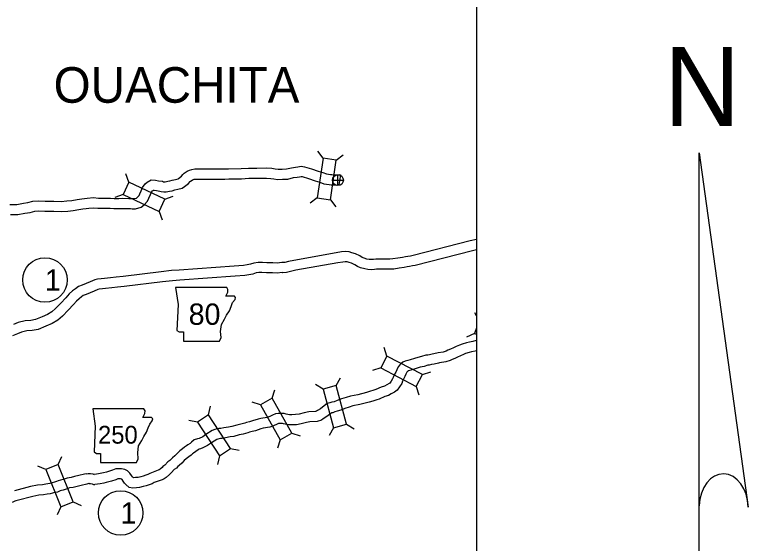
# Model space of a CAD drawing. Extents: x 1382482 to 1385815, y 1168351 to 1170484.
# Drawn here: x 1383234.6 to 1383452.3, y 1169980.1 to 1170137 of the extents above; entities that cross this region are included whole.
import ezdxf

# ---------------------------------------------------------------- set-up
doc = ezdxf.new("R2010")
doc.units = 0
for name, color, linetype in [('10', 7, 'Continuous'), ('20', 7, 'Continuous'), ('21', 7, 'Continuous'), ('26', 7, 'Continuous'), ('8', 7, 'Continuous'), ('Default', 7, 'Continuous'), ('R_Draft', 7, 'Continuous'), ('R_No Plot', 7, 'Continuous')]:
    doc.layers.add(name, color=color, linetype=linetype)

msp = doc.modelspace()

# ---------------------------------------------------------------- linework, layer by layer
at = {"layer": '10'}
msp.add_line((1383331.28, 1170089.42), (1383330.79, 1170086.46), dxfattribs=at)
for points in [[(1383233.12, 1170080.63), (1383235.23, 1170080.67), (1383237.16, 1170080.99), (1383238.51, 1170081.19), (1383239.97, 1170081.62), (1383241.64, 1170081.75), (1383243.59, 1170081.61), (1383246.24, 1170081.64), (1383248.38, 1170081.51), (1383250.08, 1170081.67), (1383251.52, 1170081.82), (1383253.16, 1170082.09), (1383254.48, 1170082.31), (1383255.33, 1170082.37), (1383256.11, 1170082.53), (1383257.99, 1170082.69), (1383259.45, 1170082.54), (1383261.24, 1170082.52), (1383262.99, 1170082.49), (1383264.08, 1170082.43), (1383265.44, 1170082.44), (1383266.66, 1170082.46), (1383268.48, 1170082.42), (1383269.06, 1170082.42), (1383269.61, 1170082.38), (1383270.13, 1170082.36), (1383270.76, 1170082.53), (1383270.92, 1170082.66), (1383271.49, 1170083.31), (1383271.7, 1170083.77), (1383272.12, 1170084.68), (1383272.48, 1170085.7), (1383273.27, 1170086.74), (1383273.93, 1170087.28), (1383275.05, 1170087.95), (1383276.39, 1170087.88), (1383277.24, 1170087.69), (1383278.41, 1170087.51), (1383278.74, 1170087.39), (1383278.94, 1170087.37), (1383279.26, 1170087.38), (1383280.01, 1170087.51), (1383280.64, 1170087.62), (1383281.32, 1170087.84), (1383282.29, 1170088.08), (1383283.11, 1170088.27), (1383283.23, 1170088.34), (1383284.07, 1170089.05), (1383284.47, 1170089.49), (1383284.88, 1170089.93), (1383285.79, 1170090.48), (1383286.45, 1170090.79), (1383287.12, 1170091.02), (1383288.09, 1170091.18), (1383290.2, 1170091.18), (1383296.87, 1170091.16), (1383298.06, 1170091.25), (1383301.82, 1170091.28), (1383304, 1170091.42), (1383305.23, 1170091.42), (1383306.43, 1170091.44), (1383309.39, 1170091.47), (1383310.93, 1170091.36), (1383311.88, 1170091.21), (1383312.77, 1170091.09), (1383313.98, 1170091.14), (1383315.24, 1170091.17), (1383316.69, 1170091.53), (1383317.93, 1170091.74), (1383318.65, 1170091.85), (1383319.63, 1170091.98), (1383320.57, 1170091.81), (1383322.72, 1170091.16), (1383324.7, 1170090.48), (1383326.08, 1170090.08), (1383327.1, 1170089.7), (1383328.27, 1170089.54), (1383328.74, 1170089.49), (1383329.5, 1170089.46), (1383330.15, 1170089.42), (1383330.93, 1170089.49), (1383331.28, 1170089.42)], [(1383233.32, 1170077.63), (1383235.51, 1170077.68), (1383237.63, 1170078.02), (1383239.16, 1170078.25), (1383240.51, 1170078.65), (1383241.65, 1170078.74), (1383243.5, 1170078.61), (1383246.16, 1170078.64), (1383248.44, 1170078.5), (1383250.39, 1170078.69), (1383251.92, 1170078.85), (1383253.65, 1170079.13), (1383254.82, 1170079.33), (1383255.75, 1170079.39), (1383256.55, 1170079.56), (1383257.97, 1170079.68), (1383259.28, 1170079.55), (1383261.2, 1170079.52), (1383262.88, 1170079.49), (1383264.01, 1170079.42), (1383265.49, 1170079.44), (1383266.66, 1170079.46), (1383268.44, 1170079.42), (1383268.95, 1170079.42), (1383269.47, 1170079.38), (1383270.47, 1170079.35), (1383272.16, 1170079.79), (1383273.02, 1170080.5), (1383274.02, 1170081.66), (1383274.42, 1170082.5), (1383274.91, 1170083.55), (1383275.16, 1170084.26), (1383275.44, 1170084.65), (1383275.65, 1170084.82), (1383275.8, 1170084.91), (1383275.98, 1170084.9), (1383276.69, 1170084.74), (1383277.65, 1170084.6), (1383278.03, 1170084.45), (1383278.82, 1170084.36), (1383279.57, 1170084.38), (1383280.52, 1170084.55), (1383281.36, 1170084.7), (1383282.15, 1170084.95), (1383282.99, 1170085.17), (1383284.29, 1170085.46), (1383285, 1170085.92), (1383286.14, 1170086.87), (1383286.67, 1170087.44), (1383286.79, 1170087.57), (1383287.23, 1170087.84), (1383287.58, 1170088.01), (1383287.85, 1170088.1), (1383288.35, 1170088.18), (1383290.2, 1170088.18), (1383296.97, 1170088.16), (1383298.17, 1170088.25), (1383301.93, 1170088.28), (1383304.1, 1170088.42), (1383305.26, 1170088.42), (1383306.47, 1170088.44), (1383309.3, 1170088.47), (1383310.59, 1170088.38), (1383311.45, 1170088.24), (1383312.63, 1170088.08), (1383314.08, 1170088.14), (1383315.64, 1170088.18), (1383317.29, 1170088.59), (1383318.4, 1170088.77), (1383319.08, 1170088.88), (1383319.56, 1170088.94), (1383319.87, 1170088.89), (1383321.79, 1170088.31), (1383323.79, 1170087.62), (1383325.15, 1170087.22), (1383326.37, 1170086.78), (1383327.9, 1170086.56), (1383328.53, 1170086.49), (1383329.35, 1170086.46), (1383330.19, 1170086.41), (1383330.79, 1170086.46)], [(1383371.62, 1170070.23), (1383369.73, 1170069.81), (1383352.84, 1170065.49), (1383352.07, 1170065.34), (1383351.24, 1170065.19), (1383350.59, 1170065.1), (1383349.65, 1170064.92), (1383348.25, 1170064.67), (1383346.81, 1170064.46), (1383345.88, 1170064.42), (1383344.7, 1170064.42), (1383343.82, 1170064.41), (1383342.69, 1170064.44), (1383341.79, 1170064.42), (1383341.07, 1170064.35), (1383340.32, 1170064.29), (1383339.76, 1170064.33), (1383339.11, 1170064.44), (1383338.26, 1170064.66), (1383337.72, 1170064.92), (1383336.98, 1170065.36), (1383335.69, 1170065.97), (1383334.68, 1170066.32), (1383333.81, 1170066.53), (1383332.68, 1170066.66), (1383331.6, 1170066.53), (1383330.04, 1170066.33), (1383317.47, 1170064.05), (1383315.83, 1170063.69), (1383314.76, 1170063.45), (1383314.06, 1170063.4), (1383313.83, 1170063.4), (1383312.44, 1170063.23), (1383311.19, 1170063.31), (1383309.46, 1170063.32), (1383308.12, 1170063.41), (1383306.87, 1170063.45), (1383305.58, 1170063.22), (1383304.55, 1170062.9), (1383303.55, 1170062.69), (1383302.52, 1170062.55), (1383299.76, 1170062.34), (1383283.39, 1170061.17), (1383281.08, 1170061), (1383278.07, 1170060.64), (1383266.76, 1170059.26), (1383264.72, 1170059.03), (1383263.06, 1170058.84), (1383261.25, 1170058.66), (1383260.28, 1170058.58), (1383259.13, 1170058.43), (1383258.32, 1170058.24), (1383256.99, 1170057.71), (1383254.6, 1170056.72), (1383253.48, 1170056.26), (1383252.59, 1170055.63), (1383251.78, 1170055), (1383250.75, 1170054.1), (1383249.75, 1170052.95), (1383248.3, 1170051.31), (1383246.68, 1170049.72), (1383245.58, 1170048.74), (1383244.34, 1170047.96), (1383242.69, 1170047.31), (1383240.72, 1170046.46), (1383239.34, 1170046.24), (1383237.71, 1170046.09), (1383235.65, 1170045.61), (1383234.26, 1170044.99)], [(1383371.62, 1170067.16), (1383370.43, 1170066.89), (1383353.49, 1170062.56), (1383352.61, 1170062.39), (1383351.72, 1170062.23), (1383351.08, 1170062.14), (1383350.19, 1170061.97), (1383348.73, 1170061.71), (1383347.09, 1170061.47), (1383345.94, 1170061.42), (1383344.72, 1170061.42), (1383343.8, 1170061.41), (1383342.68, 1170061.44), (1383341.98, 1170061.42), (1383341.34, 1170061.36), (1383340.34, 1170061.28), (1383339.4, 1170061.35), (1383338.49, 1170061.5), (1383337.24, 1170061.82), (1383336.29, 1170062.27), (1383335.56, 1170062.71), (1383334.56, 1170063.18), (1383333.83, 1170063.43), (1383333.28, 1170063.57), (1383332.69, 1170063.64), (1383331.97, 1170063.55), (1383330.5, 1170063.36), (1383318.06, 1170061.11), (1383316.48, 1170060.76), (1383315.21, 1170060.48), (1383314.12, 1170060.39), (1383313.95, 1170060.4), (1383312.53, 1170060.22), (1383311.08, 1170060.31), (1383309.36, 1170060.33), (1383307.97, 1170060.41), (1383307.09, 1170060.44), (1383306.29, 1170060.3), (1383305.29, 1170059.99), (1383304.07, 1170059.74), (1383302.84, 1170059.56), (1383299.97, 1170059.35), (1383283.6, 1170058.18), (1383281.37, 1170058.02), (1383278.43, 1170057.66), (1383267.11, 1170056.28), (1383265.05, 1170056.05), (1383263.38, 1170055.86), (1383261.52, 1170055.67), (1383260.59, 1170055.6), (1383259.67, 1170055.47), (1383259.21, 1170055.37), (1383258.12, 1170054.93), (1383255.75, 1170053.95), (1383254.94, 1170053.61), (1383254.38, 1170053.22), (1383253.69, 1170052.68), (1383252.88, 1170051.98), (1383252.01, 1170050.97), (1383250.48, 1170049.25), (1383248.73, 1170047.53), (1383247.39, 1170046.33), (1383245.7, 1170045.28), (1383243.83, 1170044.54), (1383241.56, 1170043.56), (1383239.72, 1170043.26), (1383238.19, 1170043.12), (1383236.61, 1170042.76), (1383235.42, 1170042.22), (1383233.91, 1170041.64)], [(1383371.62, 1170040.29), (1383371.5, 1170040.26), (1383370.59, 1170039.99), (1383369.54, 1170039.8), (1383368.67, 1170039.61), (1383367.4, 1170039.21), (1383366.62, 1170038.92), (1383365.65, 1170038.46), (1383364.79, 1170038.09), (1383363.93, 1170037.68), (1383363.17, 1170037.35), (1383362.68, 1170037.12), (1383361.79, 1170036.81), (1383360.31, 1170036.58), (1383359.87, 1170036.54), (1383358.46, 1170036.2), (1383357.71, 1170036.05), (1383357.21, 1170035.94), (1383356.62, 1170035.9), (1383355.35, 1170035.47), (1383354.26, 1170035.24), (1383353.21, 1170034.95), (1383351.96, 1170034.55), (1383351.29, 1170034.35), (1383350.51, 1170034.1), (1383349.83, 1170033.86), (1383349.19, 1170033.32), (1383348.93, 1170033.09), (1383348.42, 1170032.48), (1383347.97, 1170031.61), (1383347.66, 1170030.91), (1383347.22, 1170030.08), (1383346.9, 1170029.28), (1383346.74, 1170028.85), (1383346.33, 1170028.17), (1383345.92, 1170027.62), (1383345.73, 1170027.46), (1383345.01, 1170027.12), (1383344.3, 1170026.74), (1383343.39, 1170026.41), (1383341.73, 1170025.7), (1383341.19, 1170025.54), (1383339.92, 1170025.13), (1383339.01, 1170024.85), (1383336.38, 1170024.16), (1383334.23, 1170023.76), (1383332.95, 1170023.38), (1383331.53, 1170022.91), (1383330.32, 1170022.45), (1383329.4, 1170022.11), (1383328.73, 1170021.93), (1383328.13, 1170021.73), (1383327.32, 1170021.54), (1383326.46, 1170020.88), (1383325.3, 1170020.01), (1383324.42, 1170019.49), (1383324.19, 1170019.3), (1383323.85, 1170019.2), (1383321.84, 1170019.08), (1383320.49, 1170018.84), (1383318.98, 1170018.45), (1383317.92, 1170018.26), (1383316.76, 1170018.2)], [(1383371.62, 1170037.17), (1383371.29, 1170037.07), (1383370.13, 1170036.86), (1383369.45, 1170036.71), (1383368.37, 1170036.36), (1383367.78, 1170036.15), (1383366.9, 1170035.73), (1383366.03, 1170035.35), (1383365.17, 1170034.95), (1383364.41, 1170034.62), (1383363.79, 1170034.33), (1383362.52, 1170033.89), (1383360.68, 1170033.6), (1383360.35, 1170033.57), (1383359.11, 1170033.27), (1383358.32, 1170033.11), (1383357.63, 1170032.96), (1383357.22, 1170032.94), (1383356.14, 1170032.57), (1383354.96, 1170032.32), (1383354.07, 1170032.08), (1383352.86, 1170031.69), (1383352.18, 1170031.48), (1383351.45, 1170031.25), (1383351.35, 1170031.22), (1383351.14, 1170031.03), (1383351.07, 1170030.98), (1383350.94, 1170030.82), (1383350.67, 1170030.3), (1383350.36, 1170029.61), (1383349.95, 1170028.82), (1383349.69, 1170028.19), (1383349.45, 1170027.53), (1383348.82, 1170026.5), (1383348.12, 1170025.55), (1383347.35, 1170024.91), (1383346.36, 1170024.44), (1383345.54, 1170023.99), (1383344.48, 1170023.62), (1383342.74, 1170022.87), (1383342.07, 1170022.67), (1383340.83, 1170022.28), (1383339.83, 1170021.96), (1383337.03, 1170021.23), (1383334.93, 1170020.84), (1383333.86, 1170020.52), (1383332.54, 1170020.08), (1383331.36, 1170019.64), (1383330.31, 1170019.25), (1383329.59, 1170019.06), (1383328.96, 1170018.85), (1383328.63, 1170018.77), (1383328.27, 1170018.49), (1383326.97, 1170017.52), (1383326.14, 1170017.02), (1383325.63, 1170016.61), (1383324.4, 1170016.22), (1383322.19, 1170016.1), (1383321.14, 1170015.91), (1383319.62, 1170015.51), (1383318.26, 1170015.27), (1383316.92, 1170015.21)], [(1383316.88, 1170018.2), (1383316.16, 1170018.22), (1383315.15, 1170018.41), (1383314.52, 1170018.64), (1383312.73, 1170018.61), (1383311.95, 1170018.55), (1383311.08, 1170018.06), (1383310.33, 1170017.7), (1383309.56, 1170017.46), (1383307.68, 1170017.15), (1383306.8, 1170016.89), (1383305.18, 1170016.38), (1383304.25, 1170016.13), (1383303.39, 1170015.9), (1383302.85, 1170015.72), (1383301.7, 1170015.41), (1383300.49, 1170015.15), (1383299.02, 1170014.76), (1383298.01, 1170014.59), (1383296.63, 1170014.35), (1383295.73, 1170014.2), (1383295.13, 1170014.14), (1383294.02, 1170013.87), (1383293.19, 1170013.55), (1383291.35, 1170012.35), (1383290.37, 1170011.68), (1383289.3, 1170011.18), (1383288.88, 1170011.04), (1383287.89, 1170010.8), (1383287.08, 1170010.09), (1383286.66, 1170009.74), (1383285.97, 1170009.33), (1383285.54, 1170009.03), (1383285, 1170008.58), (1383284.4, 1170008.09), (1383283.59, 1170007.5), (1383282.76, 1170006.73), (1383282.1, 1170006), (1383281.45, 1170005.47), (1383280.9, 1170005), (1383280.61, 1170004.66), (1383279.99, 1170004.27), (1383279.1, 1170003.28), (1383278.59, 1170002.87), (1383278.36, 1170002.58), (1383277.79, 1170002.08), (1383277.46, 1170001.88), (1383277.17, 1170001.74), (1383276.13, 1170001.39), (1383274.69, 1170000.81), (1383274.12, 1170000.51), (1383273.49, 1170000.28), (1383272.71, 1170000), (1383272.01, 1169999.82), (1383271.18, 1169999.64), (1383270.4, 1169999.57), (1383269.84, 1169999.51), (1383269.73, 1169999.61), (1383269.59, 1169999.78), (1383269.26, 1170000.24), (1383268.8, 1170000.94), (1383268.08, 1170001.61), (1383267.23, 1170001.99), (1383266.31, 1170002.22), (1383265.46, 1170002.19), (1383264.58, 1170002.14), (1383263.58, 1170001.77), (1383262.41, 1170001.35), (1383261.81, 1170001.2), (1383260.95, 1170000.98), (1383260.44, 1170000.85), (1383259.46, 1170000.69), (1383258.82, 1170000.59), (1383258.21, 1170000.55)], [(1383316.8, 1170015.2), (1383315.84, 1170015.23), (1383314.35, 1170015.51), (1383314.02, 1170015.63), (1383312.88, 1170015.61), (1383312.84, 1170015.61), (1383312.46, 1170015.4), (1383311.44, 1170014.9), (1383310.26, 1170014.54), (1383308.35, 1170014.22), (1383307.68, 1170014.02), (1383306.02, 1170013.5), (1383305.02, 1170013.22), (1383304.26, 1170013.03), (1383303.73, 1170012.85), (1383302.39, 1170012.49), (1383301.19, 1170012.24), (1383299.66, 1170011.82), (1383298.51, 1170011.63), (1383297.13, 1170011.39), (1383296.13, 1170011.23), (1383295.63, 1170011.17), (1383294.91, 1170011), (1383294.56, 1170010.87), (1383293.02, 1170009.86), (1383291.85, 1170009.06), (1383290.4, 1170008.39), (1383289.71, 1170008.16), (1383289.32, 1170008.06), (1383289.03, 1170007.81), (1383288.39, 1170007.28), (1383287.6, 1170006.81), (1383287.38, 1170006.65), (1383286.92, 1170006.27), (1383286.24, 1170005.71), (1383285.5, 1170005.18), (1383284.89, 1170004.61), (1383284.17, 1170003.82), (1383283.37, 1170003.16), (1383283.03, 1170002.88), (1383282.61, 1170002.37), (1383281.94, 1170001.95), (1383281.16, 1170001.08), (1383280.72, 1170000.74), (1383280.54, 1170000.5), (1383279.57, 1169999.66), (1383278.91, 1169999.25), (1383278.32, 1169998.96), (1383277.17, 1169998.57), (1383275.95, 1169998.08), (1383275.34, 1169997.76), (1383274.52, 1169997.46), (1383273.59, 1169997.12), (1383272.7, 1169996.9), (1383271.64, 1169996.67), (1383270.69, 1169996.58), (1383269.61, 1169996.47), (1383268.56, 1169996.67), (1383267.57, 1169997.5), (1383267.2, 1169997.96), (1383266.78, 1169998.54), (1383266.49, 1169998.99), (1383266.4, 1169999.08), (1383266.25, 1169999.14), (1383265.99, 1169999.21), (1383265.58, 1169999.2), (1383265.21, 1169999.17), (1383264.61, 1169998.95), (1383263.28, 1169998.48), (1383262.54, 1169998.3), (1383261.69, 1169998.08), (1383261.06, 1169997.91), (1383259.95, 1169997.73), (1383259.15, 1169997.6), (1383258.38, 1169997.56)], [(1383255.81, 1170000.72), (1383255.76, 1170000.71), (1383255.26, 1170000.59), (1383253.61, 1170000.18), (1383252.36, 1169999.88), (1383251.37, 1169999.63), (1383250.13, 1169999.42), (1383248.96, 1169999.01), (1383248.18, 1169998.81), (1383247.5, 1169998.64), (1383246.95, 1169998.42), (1383246.4, 1169998.18), (1383245.74, 1169998.05), (1383245, 1169997.87), (1383244.43, 1169997.69), (1383243.77, 1169997.6), (1383242.83, 1169997.44), (1383241.32, 1169997.37), (1383239.26, 1169996.93), (1383234.47, 1169995.69)], [(1383255.81, 1170000.72), (1383256.35, 1170000.77), (1383257.06, 1170000.77), (1383257.74, 1170000.67), (1383258.21, 1170000.55)], [(1383256.69, 1169997.85), (1383256.54, 1169997.81), (1383255.96, 1169997.67), (1383254.33, 1169997.27), (1383253.07, 1169996.96), (1383251.97, 1169996.69), (1383250.88, 1169996.51), (1383249.84, 1169996.14), (1383248.92, 1169995.9), (1383248.43, 1169995.78), (1383248.11, 1169995.65), (1383247.29, 1169995.29), (1383246.39, 1169995.12), (1383245.82, 1169994.98), (1383245.08, 1169994.74), (1383244.22, 1169994.63), (1383243.15, 1169994.45), (1383241.7, 1169994.39), (1383239.95, 1169994.01), (1383235.31, 1169992.81), (1383234.92, 1169992.68), (1383234.62, 1169992.57), (1383233.83, 1169992.24)], [(1383256.69, 1169997.85), (1383257.06, 1169997.85), (1383257.56, 1169997.7), (1383257.94, 1169997.52), (1383258.38, 1169997.56)]]:
    msp.add_lwpolyline(points, dxfattribs=at)
at = {"layer": '20'}
for p, q in [((1383326.09, 1170094.34), (1383324.51, 1170096.45)), ((1383330.01, 1170093.77), (1383332.12, 1170095.35)), ((1383268.42, 1170087.22), (1383267.52, 1170089.7)), ((1383266.73, 1170083.63), (1383264.25, 1170082.74)), ((1383279.17, 1170082.17), (1383281.65, 1170083.07)), ((1383324.38, 1170082.58), (1383322.26, 1170081)), ((1383328.3, 1170082.01), (1383329.88, 1170079.9)), ((1383277.49, 1170078.58), (1383278.38, 1170076.1)), ((1383371.62, 1170047.56), (1383371.17, 1170048.49)), ((1383371.05, 1170042.37), (1383368.68, 1170041.21)), ((1383345.07, 1170035.66), (1383344.28, 1170038.18)), ((1383343.24, 1170032.15), (1383340.73, 1170031.35)), ((1383355.61, 1170030.17), (1383358.13, 1170030.97)), ((1383329.98, 1170026.87), (1383331.3, 1170029.16)), ((1383326.16, 1170025.84), (1383323.87, 1170027.16)), ((1383353.78, 1170026.66), (1383354.57, 1170024.14)), ((1383311.04, 1170023.12), (1383311.77, 1170025.66)), ((1383307.58, 1170021.2), (1383305.04, 1170021.93)), ((1383292.14, 1170018.17), (1383292.68, 1170020.76)), ((1383288.83, 1170016.01), (1383286.24, 1170016.55)), ((1383333.07, 1170015.4), (1383335.36, 1170014.08)), ((1383316.81, 1170012.73), (1383319.35, 1170012.01)), ((1383329.25, 1170014.37), (1383327.93, 1170012.08)), ((1383313.35, 1170010.81), (1383312.62, 1170008.28)), ((1383298.64, 1170008.23), (1383301.23, 1170007.69)), ((1383247.5, 1170003.42), (1383248.54, 1170005.85)), ((1383295.33, 1170006.06), (1383294.79, 1170003.48)), ((1383243.83, 1170001.95), (1383241.4, 1170002.99)), ((1383251.91, 1169992.39), (1383254.34, 1169991.35)), ((1383248.23, 1169990.92), (1383247.19, 1169988.49))]:
    msp.add_line(p, q, dxfattribs=at)
for points in [[(1383328.3, 1170082.01), (1383330.01, 1170093.77), (1383326.09, 1170094.34), (1383324.38, 1170082.58)], [(1383266.73, 1170083.63), (1383277.49, 1170078.58), (1383279.17, 1170082.17), (1383268.42, 1170087.22)], [(1383355.61, 1170030.17), (1383345.07, 1170035.66), (1383343.24, 1170032.15), (1383353.78, 1170026.66)], [(1383326.16, 1170025.84), (1383329.25, 1170014.37), (1383333.07, 1170015.4), (1383329.98, 1170026.87)], [(1383307.58, 1170021.2), (1383313.35, 1170010.81), (1383316.81, 1170012.73), (1383311.04, 1170023.12)], [(1383288.83, 1170016.01), (1383295.33, 1170006.06), (1383298.64, 1170008.23), (1383292.14, 1170018.17)], [(1383243.83, 1170001.95), (1383248.23, 1169990.92), (1383251.91, 1169992.39), (1383247.5, 1170003.42)]]:
    msp.add_lwpolyline(points, close=True, dxfattribs=at)
msp.add_lwpolyline([(1383371.62, 1170044.05), (1383371.05, 1170042.37), (1383371.62, 1170042.18)], dxfattribs=at)
at = {"layer": '21'}
for points in [[(1383282.32, 1170055.98), (1383283.08, 1170050.91), (1383282.74, 1170043.21), (1383283.42, 1170042.79), (1383284.68, 1170042.79), (1383284.68, 1170040.08), (1383295.34, 1170040.08), (1383295.85, 1170041.18), (1383295.68, 1170042.96), (1383295.94, 1170044.99), (1383296.87, 1170046.59), (1383297.46, 1170047.78), (1383298.3, 1170049.05), (1383298.81, 1170050.4), (1383299.23, 1170051.5), (1383300, 1170052.43), (1383300.16, 1170053.02), (1383299.83, 1170053.45), (1383297.2, 1170053.45), (1383297.8, 1170054.63), (1383297.88, 1170055.39), (1383297.53, 1170055.98)], [(1383257.72, 1170019.96), (1383258.48, 1170014.88), (1383258.15, 1170007.18), (1383258.82, 1170006.76), (1383260.09, 1170006.76), (1383260.09, 1170004.05), (1383270.75, 1170004.05), (1383271.26, 1170005.15), (1383271.09, 1170006.93), (1383271.34, 1170008.96), (1383272.27, 1170010.57), (1383272.87, 1170011.75), (1383273.71, 1170013.02), (1383274.22, 1170014.37), (1383274.64, 1170015.47), (1383275.4, 1170016.4), (1383275.57, 1170017), (1383275.23, 1170017.42), (1383272.61, 1170017.42), (1383273.2, 1170018.6), (1383273.29, 1170019.36), (1383272.94, 1170019.95)]]:
    msp.add_lwpolyline(points, close=True, dxfattribs=at)
at = {"layer": '26'}
for p, q in [((1383330.53, 1170086.22), (1383330.53, 1170089.47)), ((1383328.9, 1170087.84), (1383332.15, 1170087.84))]:
    msp.add_line(p, q, dxfattribs=at)
msp.add_circle((1383330.53, 1170087.84), 1.62, dxfattribs=at)
at = {"layer": 'Default'}
for centre in [(1383243.55, 1170058.23), (1383266.02, 1169989.1)]:
    msp.add_circle(centre, 6.6, dxfattribs=at)
at = {"layer": 'R_Draft'}
for p, q in [((1383437.78, 1170095.98), (1383452.33, 1169990.81)), ((1383437.78, 1169969.86), (1383437.78, 1170095.98))]:
    msp.add_line(p, q, dxfattribs=at)
msp.add_ellipse((1383445.05, 1169990.58), major_axis=(-0.31, 10.11), ratio=0.719778, start_param=4.712385, end_param=7.768526, dxfattribs=at)
at = {"layer": 'R_No Plot'}
msp.add_lwpolyline([(1382642.23, 1170388.77), (1383371.62, 1170388.77), (1383371.62, 1169604.28), (1382642.23, 1169604.28)], close=True, dxfattribs=at)

# ---------------------------------------------------------------- texts
at = {"layer": '21'}
for s, height, p in [('80', 6.336, (1383286.22, 1170044.91)), ('250', 5.28, (1383259.31, 1170009.66))]:
    msp.add_text(s, height=height, dxfattribs=at).set_placement(p)
at = {"layer": '8'}
msp.add_text('OUACHITA', height=10.56, dxfattribs=at).set_placement((1383246.13, 1170110.82))
at = {"layer": 'Default'}
for p in [(1383243.55, 1170055.07), (1383266.02, 1169985.93)]:
    msp.add_text('1', height=6.34, dxfattribs=at).set_placement(p)
at = {"layer": 'R_Draft'}
msp.add_text('N', height=23.47, dxfattribs=at).set_placement((1383427.31, 1170103.92))

doc.saveas('drawing.dxf')
